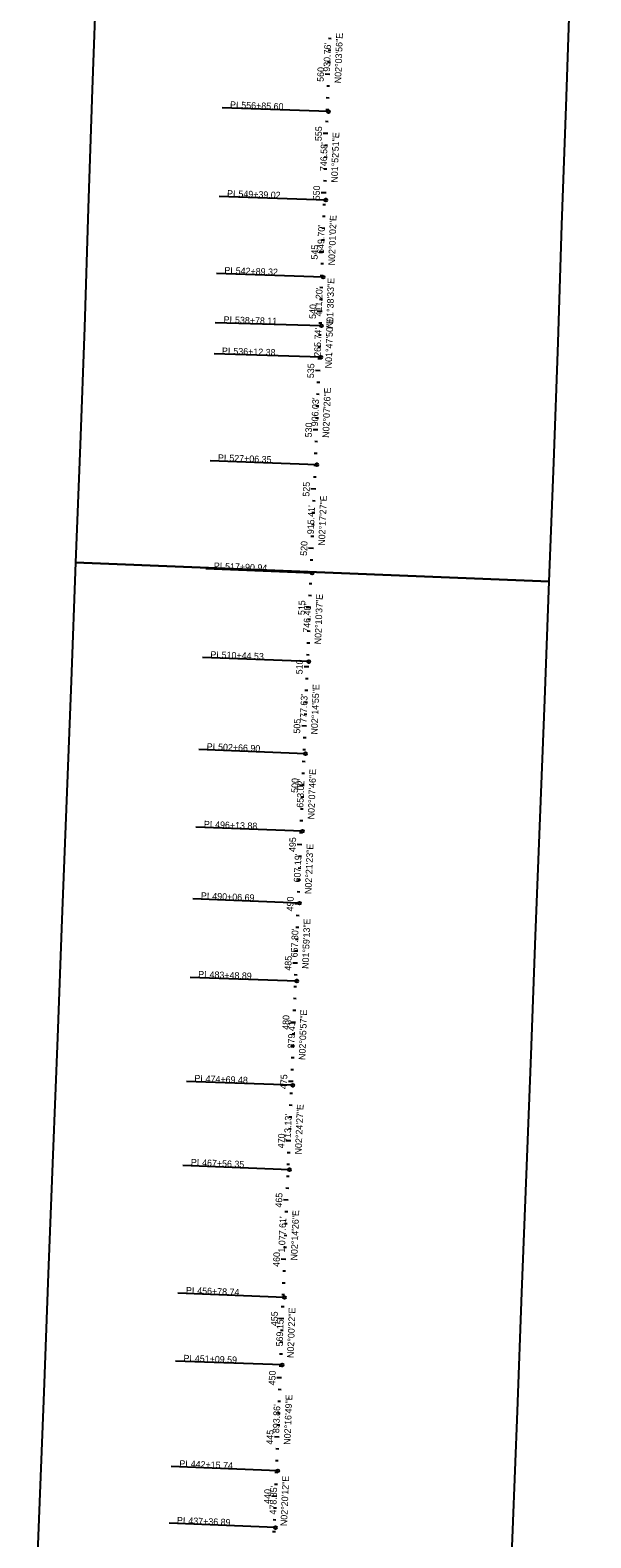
# Model space of a CAD drawing. Extents: x 1697889 to 1709091, y 242468 to 292801.
# Drawn here: x 1700412 to 1705144, y 255128 to 267842 of the extents above; entities that cross this region are included whole.
import ezdxf

# ---------------------------------------------------------------- set-up
doc = ezdxf.new("R2010")
doc.units = 0
for name, color, linetype in [('SC_Scratch1', 7, 'Continuous'), ('XS_P_Finished_Grade', 7, 'Continuous'), ('XS_P_Headwall', 7, 'Continuous'), ('XS_P_Pavt_Surface', 7, 'Continuous'), ('XS_P_Shoulder_Layers', 7, 'Continuous')]:
    doc.layers.add(name, color=color, linetype=linetype)

msp = doc.modelspace()

# ---------------------------------------------------------------- linework, layer by layer
at = {"layer": 'SC_Scratch1'}
for points in [[(1700795, 263352), (1704792, 263192), (1704832, 264197), (1704868, 265207), (1704900, 266199), (1704934, 267197), (1704970, 268198), (1705004, 269201), (1705040, 270202), (1705070, 271205), (1705107, 272187), (1705144, 273201), (1701146, 273330), (1701110, 272345), (1701072, 271329), (1701042, 270333), (1701007, 269335), (1700972, 268339), (1700936, 267341), (1700903, 266340), (1700870, 265333), (1700835, 264345)], [(1700412, 253361), (1704409, 253197), (1704447, 254203), (1704484, 255196), (1704524, 256197), (1704561, 257198), (1704600, 258191), (1704641, 259201), (1704677, 260205), (1704716, 261199), (1704754, 262194), (1704792, 263192), (1700795, 263352), (1700757, 262351), (1700719, 261347), (1700679, 260343), (1700644, 259348), (1700604, 258359), (1700564, 257354), (1700528, 256356), (1700487, 255359), (1700450, 254354)]]:
    msp.add_lwpolyline(points, close=True, dxfattribs=at)
at = {"layer": 'XS_P_Finished_Grade'}
for p, q in [((1702931, 267155), (1702032, 267187)), ((1702907, 266409), (1702007, 266438)), ((1702884, 265759), (1701984, 265791)), ((1702872, 265348), (1701972, 265374)), ((1702864, 265083), (1701964, 265111)), ((1702830, 264177), (1701931, 264211)), ((1702793, 263263), (1701894, 263299)), ((1702765, 262517), (1701866, 262551)), ((1702735, 261740), (1701835, 261775)), ((1702710, 261087), (1701811, 261121)), ((1702685, 260480), (1701786, 260517)), ((1702663, 259823), (1701763, 259854)), ((1702630, 258944), (1701731, 258977)), ((1702600, 258232), (1701701, 258269)), ((1702558, 257155), (1701659, 257190)), ((1702538, 256586), (1701639, 256618)), ((1702503, 255693), (1701603, 255729)), ((1702483, 255214), (1701584, 255251))]:
    msp.add_line(p, q, dxfattribs=at)
for centre in [(1702931, 267155), (1702907, 266409), (1702884, 265759), (1702872, 265348), (1702864, 265083), (1702830, 264177), (1702793, 263263), (1702765, 262517), (1702735, 261740), (1702710, 261087), (1702685, 260480), (1702663, 259823), (1702630, 258944), (1702600, 258232), (1702558, 257155), (1702538, 256586), (1702503, 255693), (1702483, 255214)]:
    msp.add_circle(centre, 12, dxfattribs=at)
at = {"layer": 'XS_P_Headwall'}
for p, q in [((1702953, 267769), (1702929, 267770)), ((1702950, 267669), (1702926, 267670)), ((1702946, 267569), (1702922, 267570)), ((1702942, 267469), (1702902, 267470)), ((1702939, 267369), (1702915, 267370)), ((1702935, 267269), (1702911, 267270)), ((1702932, 267169), (1702908, 267170)), ((1702928, 267069), (1702904, 267070)), ((1702925, 266969), (1702885, 266971)), ((1702922, 266869), (1702898, 266870)), ((1702918, 266769), (1702894, 266770)), ((1702915, 266669), (1702891, 266670)), ((1702912, 266569), (1702888, 266570)), ((1702909, 266470), (1702869, 266471)), ((1702905, 266370), (1702881, 266370)), ((1702902, 266270), (1702878, 266270)), ((1702898, 266170), (1702874, 266171)), ((1702891, 265970), (1702851, 265971)), ((1702895, 266070), (1702871, 266071)), ((1702888, 265870), (1702864, 265871)), ((1702884, 265770), (1702860, 265771)), ((1702881, 265670), (1702857, 265671)), ((1702875, 265470), (1702835, 265471)), ((1702878, 265570), (1702854, 265571)), ((1702873, 265370), (1702849, 265371)), ((1702869, 265270), (1702845, 265271)), ((1702866, 265170), (1702842, 265171)), ((1702859, 264970), (1702819, 264972)), ((1702863, 265070), (1702839, 265071)), ((1702856, 264870), (1702832, 264871)), ((1702852, 264770), (1702828, 264771)), ((1702845, 264571), (1702821, 264571)), ((1702848, 264671), (1702824, 264671)), ((1702841, 264471), (1702801, 264472)), ((1702837, 264371), (1702813, 264372)), ((1702833, 264271), (1702809, 264272)), ((1702826, 264071), (1702802, 264072)), ((1702830, 264171), (1702806, 264172)), ((1702822, 263971), (1702782, 263973)), ((1702818, 263871), (1702794, 263872)), ((1702814, 263771), (1702790, 263772)), ((1702806, 263571), (1702782, 263572)), ((1702810, 263671), (1702786, 263672)), ((1702802, 263471), (1702762, 263473)), ((1702798, 263372), (1702774, 263372)), ((1702790, 263172), (1702766, 263173)), ((1702794, 263272), (1702770, 263273)), ((1702786, 263072), (1702762, 263073)), ((1702782, 262972), (1702742, 262973)), ((1702779, 262872), (1702755, 262873)), ((1702771, 262672), (1702747, 262673)), ((1702775, 262772), (1702751, 262773)), ((1702767, 262572), (1702743, 262573)), ((1702763, 262472), (1702723, 262474)), ((1702759, 262372), (1702735, 262373)), ((1702752, 262172), (1702728, 262173)), ((1702755, 262272), (1702731, 262273)), ((1702748, 262072), (1702724, 262073)), ((1702744, 261973), (1702704, 261974)), ((1702736, 261773), (1702712, 261774)), ((1702740, 261873), (1702716, 261874)), ((1702732, 261673), (1702708, 261674)), ((1702728, 261573), (1702704, 261574)), ((1702725, 261473), (1702685, 261474)), ((1702717, 261273), (1702693, 261274)), ((1702721, 261373), (1702697, 261374)), ((1702713, 261173), (1702689, 261174)), ((1702710, 261073), (1702686, 261074)), ((1702706, 260973), (1702666, 260975)), ((1702697, 260773), (1702673, 260774)), ((1702701, 260873), (1702678, 260874)), ((1702693, 260674), (1702669, 260675)), ((1702689, 260574), (1702665, 260575)), ((1702685, 260474), (1702645, 260475)), ((1702682, 260374), (1702658, 260375)), ((1702678, 260274), (1702654, 260275)), ((1702675, 260174), (1702651, 260175)), ((1702671, 260074), (1702647, 260075)), ((1702668, 259974), (1702628, 259975)), ((1702664, 259874), (1702640, 259875)), ((1702661, 259774), (1702637, 259775)), ((1702657, 259674), (1702633, 259675)), ((1702653, 259574), (1702629, 259575)), ((1702650, 259474), (1702610, 259476)), ((1702646, 259374), (1702622, 259375)), ((1702642, 259274), (1702618, 259275)), ((1702639, 259175), (1702615, 259175)), ((1702631, 258975), (1702591, 258976)), ((1702635, 259075), (1702611, 259075)), ((1702627, 258875), (1702603, 258876)), ((1702623, 258775), (1702599, 258776)), ((1702619, 258675), (1702595, 258676)), ((1702611, 258475), (1702571, 258477)), ((1702615, 258575), (1702591, 258576)), ((1702606, 258375), (1702582, 258376)), ((1702602, 258275), (1702578, 258276)), ((1702598, 258175), (1702574, 258176)), ((1702590, 257976), (1702550, 257977)), ((1702594, 258075), (1702570, 258076)), ((1702586, 257876), (1702562, 257877)), ((1702582, 257776), (1702559, 257777)), ((1702579, 257676), (1702555, 257677)), ((1702571, 257476), (1702531, 257477)), ((1702575, 257576), (1702551, 257577)), ((1702567, 257376), (1702543, 257377)), ((1702563, 257276), (1702539, 257277)), ((1702555, 257076), (1702531, 257077)), ((1702559, 257176), (1702535, 257177)), ((1702552, 256976), (1702512, 256978)), ((1702548, 256876), (1702524, 256877)), ((1702545, 256776), (1702521, 256777)), ((1702538, 256576), (1702514, 256577)), ((1702541, 256676), (1702517, 256677)), ((1702534, 256477), (1702494, 256478)), ((1702530, 256377), (1702506, 256378)), ((1702526, 256277), (1702502, 256278)), ((1702518, 256077), (1702494, 256078)), ((1702522, 256177), (1702498, 256178)), ((1702514, 255977), (1702474, 255979)), ((1702510, 255877), (1702486, 255878)), ((1702502, 255677), (1702478, 255678)), ((1702506, 255777), (1702482, 255778)), ((1702498, 255577), (1702474, 255578)), ((1702494, 255477), (1702454, 255479)), ((1702490, 255377), (1702466, 255378)), ((1702482, 255178), (1702458, 255178)), ((1702486, 255278), (1702462, 255279))]:
    msp.add_line(p, q, dxfattribs=at)

# ---------------------------------------------------------------- texts
at = {"layer": 'XS_P_Finished_Grade'}
for s, rotation, p in [('PI', 357.9344, (1702098, 267186)), ('556+85.60', 357.9344, (1702193, 267182)), ('PI', 358.1191, (1702073, 266437)), ('549+39.02', 358.1191, (1702169, 266434)), ('PI', 357.9827, (1702050, 265790)), ('542+89.32', 357.9827, (1702146, 265786)), ('PI', 358.3575, (1702044, 265373)), ('538+78.11', 358.3575, (1702140, 265370)), ('PI', 358.2027, (1702030, 265110)), ('536+12.38', 358.2027, (1702126, 265107)), ('PI', 357.8762, (1701996, 264209)), ('527+06.35', 357.8762, (1702092, 264206)), ('PI', 357.7092, (1701961, 263297)), ('517+90.94', 357.7092, (1702056, 263293)), ('PI', 357.8231, (1701932, 262549)), ('510+44.53', 357.8231, (1702027, 262546)), ('PI', 357.7515, (1701901, 261773)), ('502+66.90', 357.7515, (1701997, 261770)), ('PI', 357.8706, (1701877, 261119)), ('496+13.88', 357.8706, (1701972, 261115)), ('PI', 357.6435, (1701852, 260516)), ('490+06.69', 357.6435, (1701948, 260512)), ('PI', 358.013, (1701829, 259853)), ('483+48.89', 358.013, (1701925, 259850)), ('PI', 357.9008, (1701797, 258976)), ('474+69.48', 357.9008, (1701892, 258972)), ('PI', 357.5926, (1701767, 258268)), ('467+56.35', 357.5926, (1701862, 258264)), ('PI', 357.7595, (1701726, 257188)), ('456+78.74', 357.7595, (1701821, 257185)), ('PI', 357.9939, (1701705, 256616)), ('451+09.59', 357.9939, (1701801, 256613)), ('PI', 357.7197, (1701670, 255727)), ('442+15.74', 357.7197, (1701766, 255723)), ('PI', 357.6633, (1701650, 255249)), ('437+36.89', 357.6633, (1701746, 255245))]:
    msp.add_text(s, height=56, rotation=rotation, dxfattribs=at).set_placement(p)
at = {"layer": 'XS_P_Headwall'}
for s, rotation, p in [('560', 87.9344, (1702889, 267405)), ('555', 88.1191, (1702872, 266905)), ('550', 88.1191, (1702855, 266406)), ('545', 87.9827, (1702838, 265906)), ('540', 88.3575, (1702823, 265406)), ('535', 87.8762, (1702806, 264906)), ('530', 87.8762, (1702788, 264407)), ('525', 87.7092, (1702768, 263907)), ('520', 87.7092, (1702748, 263408)), ('515', 87.8231, (1702729, 262908)), ('510', 87.7515, (1702710, 262409)), ('505', 87.7515, (1702690, 261909)), ('500', 87.8706, (1702671, 261409)), ('495', 87.6435, (1702652, 260910)), ('490', 88.013, (1702632, 260410)), ('485', 88.013, (1702615, 259910)), ('480', 87.9008, (1702596, 259411)), ('475', 87.9008, (1702578, 258911)), ('470', 87.5926, (1702557, 258412)), ('465', 87.7595, (1702537, 257912)), ('460', 87.7595, (1702517, 257412)), ('455', 87.9939, (1702499, 256912)), ('450', 87.7197, (1702480, 256413)), ('445', 87.7197, (1702461, 255913)), ('440', 87.6633, (1702440, 255414))]:
    msp.add_text(s, height=56, rotation=rotation, dxfattribs=at).set_placement(p)
at = {"layer": 'XS_P_Pavt_Surface'}
for s, rotation, p in [('N02°03\'56"E', 87.9344, (1703036, 267393)), ('N01°52\'51"E', 88.1191, (1703007, 266555)), ('N02°01\'02"E', 87.9827, (1702983, 265857)), ('N01°38\'33"E', 88.3575, (1702967, 265327)), ('N01°47\'50"E', 88.2027, (1702957, 264989)), ('N02°07\'26"E', 87.8762, (1702934, 264403)), ('N02°17\'27"E', 87.7092, (1702899, 263493)), ('N02°10\'37"E', 87.8231, (1702867, 262662)), ('N02°14\'55"E', 87.7515, (1702837, 261901)), ('N02°07\'46"E', 87.8706, (1702810, 261186)), ('N02°21\'23"E', 87.6435, (1702785, 260556)), ('N01°59\'13"E', 88.013, (1702762, 259925)), ('N02°05\'57"E', 87.9008, (1702734, 259157)), ('N02°24\'27"E', 87.5926, (1702702, 258360)), ('N02°14\'26"E', 87.7595, (1702666, 257466)), ('N02°00\'22"E', 87.9939, (1702636, 256644)), ('N02°16\'49"E', 87.7197, (1702608, 255912)), ('N02°20\'12"E', 87.6633, (1702580, 255226))]:
    msp.add_text(s, height=56, rotation=rotation, dxfattribs=at).set_placement(p)
at = {"layer": 'XS_P_Shoulder_Layers'}
for s, rotation, p in [("930.76'", 87.9344, (1702942, 267490)), ("746.58'", 88.1191, (1702914, 266652)), ("649.70'", 87.9827, (1702890, 265954)), ("411.20'", 88.3575, (1702873, 265427)), ("265.74'", 88.2027, (1702863, 265086)), ("906.03'", 87.8762, (1702841, 264500)), ("915.41'", 87.7092, (1702806, 263590)), ("746.40'", 87.8231, (1702773, 262760)), ("777.63'", 87.7515, (1702744, 261999)), ("653.02'", 87.8706, (1702717, 261284)), ("607.19'", 87.6435, (1702692, 260654)), ("657.80'", 88.013, (1702668, 260022)), ("879.41'", 87.9008, (1702641, 259254)), ("713.13'", 87.5926, (1702609, 258458)), ("1,077.61'", 87.7595, (1702562, 257532)), ("569.15'", 87.9939, (1702543, 256741)), ("893.86'", 87.7197, (1702514, 256010)), ("478.85'", 87.6633, (1702487, 255324))]:
    msp.add_text(s, height=56, rotation=rotation, dxfattribs=at).set_placement(p)

doc.saveas('drawing.dxf')
